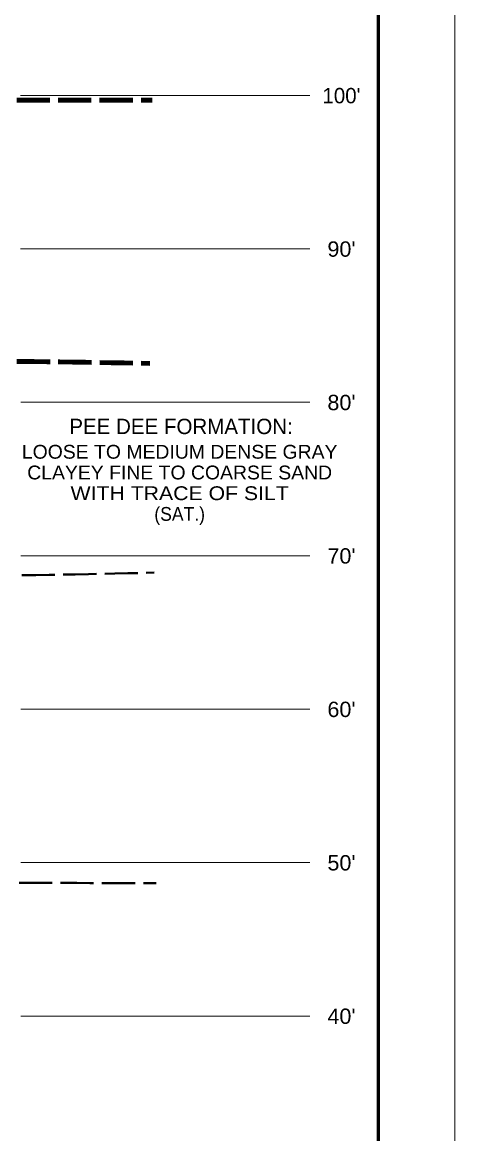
# Model space of a CAD drawing. Extents: x -76 to 974, y -1080 to -735.
# Drawn here: x 466.8 to 495, y -999.8 to -927.3 of the extents above; entities that cross this region are included whole.
import ezdxf
from ezdxf.enums import TextEntityAlignment as Align

# ---------------------------------------------------------------- set-up
doc = ezdxf.new("R2010")
doc.units = 0
doc.header["$LTSCALE"] = 0.36
doc.linetypes.add('LONG_DASHED', pattern=[7.5, 6, -1.5])
for name, color, linetype, lineweight in [('28', 7, 'LONG_DASHED', 60), ('63', 7, 'Continuous', 35), ('7', 7, 'Continuous', 13)]:
    doc.layers.add(name, color=color, linetype=linetype, lineweight=lineweight)
doc.layers.add('29', color=7, linetype='Continuous')

msp = doc.modelspace()

# ---------------------------------------------------------------- linework, layer by layer
at = {"layer": '28', "lineweight": 100}
msp.add_line((466.4353, -932.39), (475.2532, -932.39), dxfattribs=at)
msp.add_spline([(404.5082, -946.2465), (412.93, -946.1789), (416.6974, -946.1789), (419.1974, -946.1789), (455.43, -949.39), (459.1974, -949.39), (461.6974, -949.39), (475.1025, -949.549)], degree=3, dxfattribs=at)
at = {"layer": '28', "lineweight": 40}
for points in [[(404.6517, -950.267), (412.93, -950.1789), (416.6974, -950.1789), (419.1974, -950.1789), (455.43, -963.39), (459.1974, -963.39), (461.6974, -963.39), (475.3894, -963.1901)], [(404.6517, -980.1338), (412.93, -980.1789), (416.6974, -980.1789), (419.1974, -980.1789), (455.43, -983.39), (459.1974, -983.39), (461.6974, -983.39), (475.5329, -983.4363)]]:
    msp.add_spline(points, degree=3, dxfattribs=at)
at = {"layer": '63', "lineweight": 13}
msp.add_line((494.9866, -1056.1123), (494.9866, -886.1123), dxfattribs=at)
at = {"layer": '63', "lineweight": 60}
msp.add_line((489.9866, -891.4595), (489.9866, -1052.1123), dxfattribs=at)
at = {"layer": '7'}
for p, q in [((466.6703, -932.09), (485.5478, -932.09)), ((466.6887, -942.09), (485.5478, -942.09)), ((466.7019, -952.09), (485.5478, -952.09)), ((466.7019, -962.09), (485.5478, -962.09)), ((466.7019, -972.09), (485.5478, -972.09)), ((466.7019, -982.09), (485.5478, -982.09)), ((466.7019, -992.09), (485.5478, -992.09))]:
    msp.add_line(p, q, dxfattribs=at)

# ---------------------------------------------------------------- texts
at = {"layer": '29'}
msp.add_text('PEE DEE FORMATION:', height=1, dxfattribs=at).set_placement((477.1424, -954.1598), align=Align.CENTER)
for s, width, p in [('LOOSE TO MEDIUM DENSE GRAY', 1.05, (477.0542, -955.763)), ('CLAYEY FINE TO COARSE SAND', 1.05, (477.0542, -957.113)), ('WITH TRACE OF SILT', 1.15, (477.0542, -958.463)), ('(SAT.)', 0.95, (477.0543, -959.813))]:
    msp.add_text(s, height=0.9, dxfattribs=dict(at, width=width)).set_placement(p, align=Align.CENTER)
at = {"layer": '63'}
msp.add_text("100'", height=1, dxfattribs=at).set_placement((487.6009, -932.6008), align=Align.CENTER)
at = {"layer": '63', "width": 1.05}
for s, p in [("90'", (487.601, -942.6008)), ("80'", (487.601, -952.6008)), ("70'", (487.601, -962.6008)), ("60'", (487.601, -972.6008)), ("50'", (487.601, -982.6008)), ("40'", (487.601, -992.6008))]:
    msp.add_text(s, height=1, dxfattribs=at).set_placement(p, align=Align.CENTER)

doc.saveas('drawing.dxf')
